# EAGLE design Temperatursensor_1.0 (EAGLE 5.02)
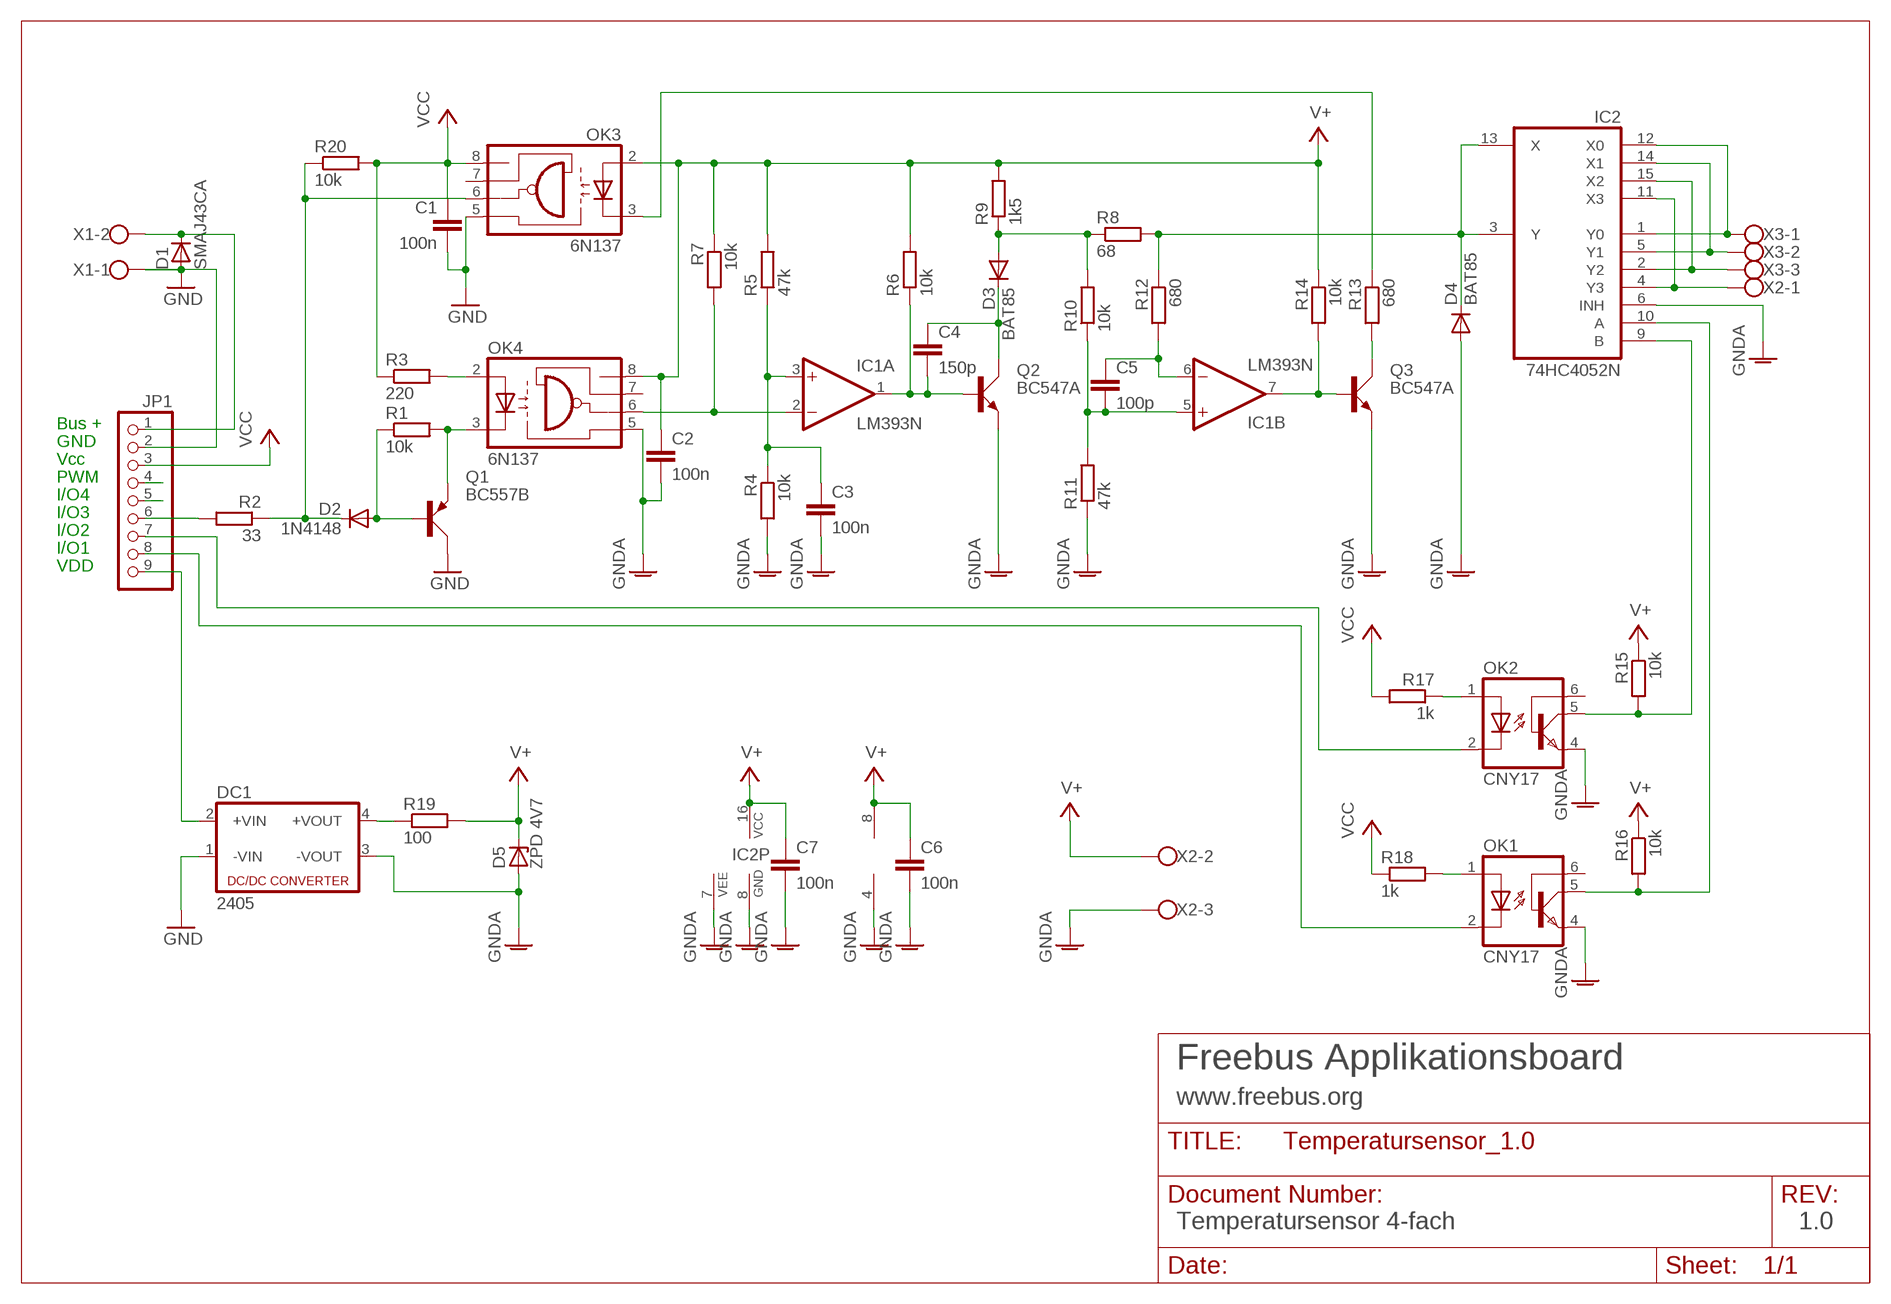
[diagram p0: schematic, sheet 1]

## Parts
C1  100n  C-EU025-024X044  [C025-024X044]
C2  100n  C-EU025-024X044  [C025-024X044]
C3  100n  C-EU025-024X044  [C025-024X044]
C4  150p  C-EU025-024X044  [C025-024X044]
C5  100p  C-EU025-024X044  [C025-024X044]
C6  100n  C-EU025-024X044  [C025-024X044]
C7  100n  C-EU025-024X044  [C025-024X044]
D1  SMAJ43CA  D-SMB  [SMB]
D2  1N4148  DIODE-D-2.5  [D-2.5]
D3  BAT85  DIODE-D-2.5  [D-2.5]
D4  BAT85  DIODE-D-7.5  [D-7.5]
D5  ZPD 4V7  ZPDSTEHEND  [ZDIODE]
DC1  2405  NME  [NME]
IC1  LM393N  [DIL08]
IC2  74HC4052N  4052N  [DIL16]
JP1  PINHD-1X9  [1X09]
OK1  CNY17  [DIL06]
OK2  CNY17  [DIL06]
OK3  6N137  HCPL2601  [DIL08]
OK4  6N137  HCPL2601  [DIL08]
Q1  BC557B  BC557  [SOT54A]
Q2  BC547A  BC547  [SOT54A]
Q3  BC547A  BC547  [SOT54A]
R1  10k  R-EU_0207/2V  [0207/2V]
R2  33  R-EU_0207/2V  [0207/2V]
R3  220  R-EU_0207/2V  [0207/2V]
R4  10k  R-EU_0207/2V  [0207/2V]
R5  47k  R-EU_0207/2V  [0207/2V]
R6  10k  R-EU_0207/2V  [0207/2V]
R7  10k  R-EU_0207/2V  [0207/2V]
R8  68  R-EU_0207/2V  [0207/2V]
R9  1k5  R-EU_0207/2V  [0207/2V]
R10  10k  R-EU_0207/2V  [0207/2V]
R11  47k  R-EU_0207/2V  [0207/2V]
R12  680  R-EU_0207/2V  [0207/2V]
R13  680  R-EU_0207/2V  [0207/2V]
R14  10k  R-EU_0207/2V  [0207/2V]
R15  10k  R-EU_0207/2V  [0207/2V]
R16  10k  R-EU_0207/2V  [0207/2V]
R17  1k  R-EU_0207/2V  [0207/2V]
R18  1k  R-EU_0207/2V  [0207/2V]
R19  100  R-EU_0207/2V  [0207/2V]
R20  10k  R-EU_0207/2V  [0207/2V]
X1  W237-02P  [W237-132]
X2  W237-3E  [W237-3E]
X3  W237-3E  [W237-3E]

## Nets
GND: C1.2 D1.2(A) DC1.1(-VIN) JP1.2 OK3.5(GND) Q1.C X1.1
GNDA: C2.2 C3.2 C6.2 C7.2 D4.A D5.A DC1.3(-VOUT) IC1.4(P:V-) IC2.6(INH) IC2.7(VEE) IC2.8(GND) OK1.4(EMI) OK2.4(EMI) OK4.5(GND) Q2.E Q3.E R4.2 R11.1 X2.3
IO1: JP1.8 OK1.2(C)
IO2: JP1.7 OK2.2(C)
IO3: JP1.6 R2.2
IO4: JP1.5
N$1: OK4.2(A) R3.2
N$2: OK4.3(C) Q1.E R1.2
N$3: D2.A Q1.B R1.1
N$4: D1.1(C) JP1.1 X1.2
N$5: D2.C OK3.6(OUT) R2.1 R20.1
N$6: IC2.1(Y0) IC2.12(X0) X3.1
N$7: IC1.2(A:-IN) OK4.6(OUT) R7.2
N$9: D4.C IC2.3(Y) IC2.13(X) R8.2 R12.1
N$10: D3.A R8.1 R9.1 R10.2
N$11: C3.1 IC1.3(A:+IN) R4.1 R5.1
N$12: IC2.5(Y1) IC2.14(X1) X3.2
N$13: C5.2 IC1.5(B:+IN) R10.1 R11.2
N$14: C4.2 IC1.1(A:OUT) Q2.B R6.1
N$15: C4.1 D3.C Q2.C
N$17: IC2.2(Y2) IC2.15(X2) X3.3
N$19: C5.1 IC1.6(B:-IN) R12.2
N$20: IC2.4(Y3) IC2.11(X3) X2.1
N$21: IC1.7(B:OUT) Q3.B R14.2
N$22: OK3.3(C) R13.1
N$23: Q3.C R13.2
N$24: IC2.9(B) OK2.5(COL) R15.2
N$25: IC2.10(A) OK1.5(COL) R16.2
N$27: OK2.1(A) R17.1
N$28: OK1.1(A) R18.2
N$29: DC1.4(+VOUT) R19.1
PWM: JP1.4
V+: C2.1 C6.1 C7.1 D5.C IC1.8(P:V+) IC2.16(VCC) OK3.2(A) OK4.8(VCC) R5.2 R6.2 R7.1 R9.2 R14.1 R15.1 R16.1 R19.2 X2.2
VCC: C1.1 JP1.3 OK3.8(VCC) R3.1 R17.2 R18.1 R20.2
VDD_IN: DC1.2(+VIN) JP1.9
Unconnected: OK1.6(BAS) OK2.6(BAS) OK3.7(EN) OK4.7(EN)

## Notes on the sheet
- Bus +
- GND
- Vcc
- PWM
- I/O4
- I/O3
- I/O2
- I/O1
- VDD
- Freebus Applikationsboard
- www.freebus.org
- Temperatursensor 4-fach | 1.0

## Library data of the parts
C1-C7 = resistor:C-EU: CAPACITOR, European symbol
D1 = semicon-smd-ipc:D-: DIODE
D2-D4 = diode:DIODE-: DIODE
D5 = diode:ZPD: Z DIODE
DC1 = dc-dc-converter:NME: DC-DC CONVERTER
IC1 = linear:LM393: COMPARATOR
IC2 = 40xx:4052: Dual 4-channel ANALOG MULTIPLEXER
JP1 = pinhead:PINHD-1X9: PIN HEADER
OK1 OK2 = optocoupler:CNY17: SIEMENS OPTO COUPLER
OK3 OK4 = optocoupler:HCPL2601: HEWLETT PACKARD OPTO COUPLER
Q1 = transistor-small-signal:BC557: PNP TRANSISTOR
Q2 Q3 = transistor-small-signal:BC547: NPN TRANSISTOR
R1-R20 = resistor:R-EU_: RESISTOR, European symbol
X1 = con-wago-508:W237-02P: WAGO SREW CLAMP
X2 X3 = con-wago-508:W237-3E: WAGO SREW CLAMP

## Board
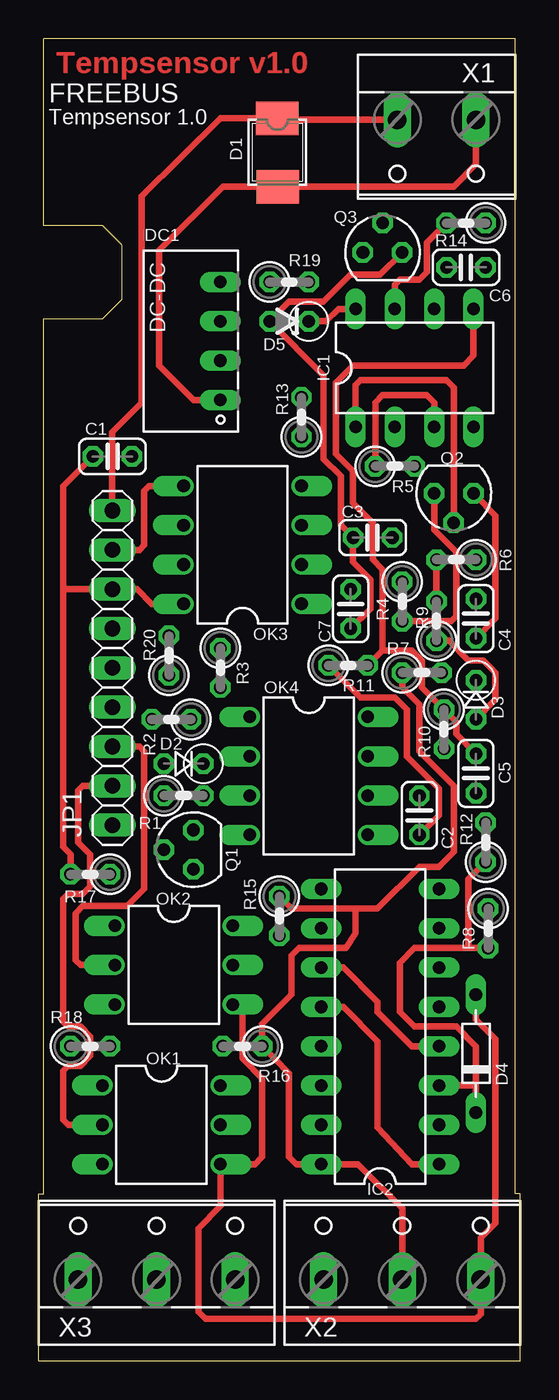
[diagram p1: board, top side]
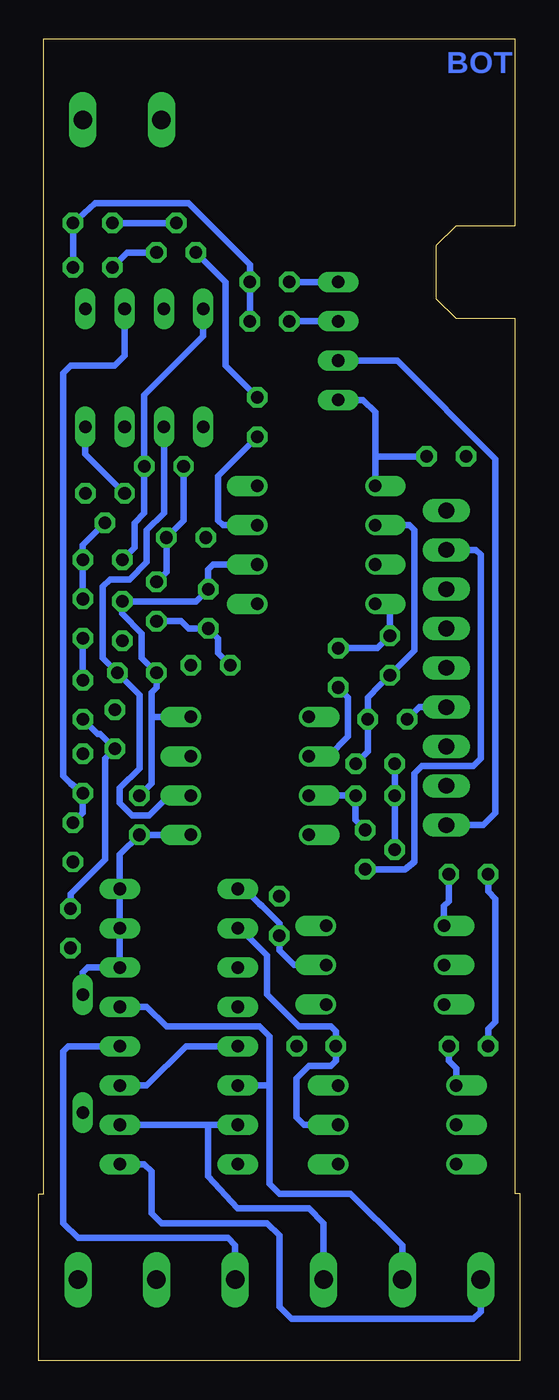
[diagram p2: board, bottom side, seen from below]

Size 31.11 x 85.41 mm. Coordinates in mm from the lower left corner, seen from the top.
Outline: 0,0 0,10.79 0.32,10.79 0.32,67.31 4.13,67.31 5.4,68.58 5.4,72.07 4.13,73.34 0.32,73.34 0.32,85.41 30.8,85.41 30.8,10.79 31.11,10.79 31.11,0 0,0
Copper layers (1*16): Top 0.035mm / dielectric 1.5mm / Bottom 0.035mm
Design rules "default *": minimum track width 10mil, minimum drill 24mil, track to track 12mil, track to pad 12mil, pad to pad 12mil, via to via 12mil, smd to smd 8mil, copper to edge 40mil, drill to drill 8mil, minimum pad ring 10mil, minimum via ring 8mil, stop-mask expansion 4mil, vias tented up to drill 0mil, thermal gap 10mil

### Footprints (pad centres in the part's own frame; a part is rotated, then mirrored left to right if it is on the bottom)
C025-024X044 = drill 0.813 octagon: 1 -1.27,0; 2 1.27,0
SMB = smd 2.159 x 2.743: 1 -2.311,-0.127; 2 2.108,-0.102
D-2.5 = drill 0.813 octagon: A 1.27,0; C -1.27,0
D-7.5 = drill 0.813 long: A 3.81,0; C -3.81,0
ZDIODE = drill 0.813 octagon: A 1.27,0; C -1.27,0
NME = drill 0.813 long: 1 0,3.81; 2 0,1.27; 3 0,-1.27; 4 0,-3.81
DIL08 = drill 0.813 long: 1 -3.81,-3.81; 2 -1.27,-3.81; 3 1.27,-3.81; 4 3.81,-3.81; 5 3.81,3.81; 6 1.27,3.81; 7 -1.27,3.81; 8 -3.81,3.81
DIL16 = drill 0.813 long: 1 -8.89,-3.81; 2 -6.35,-3.81; 3 -3.81,-3.81; 4 -1.27,-3.81; 5 1.27,-3.81; 6 3.81,-3.81; 7 6.35,-3.81; 8 8.89,-3.81; 9 8.89,3.81; 10 6.35,3.81; 11 3.81,3.81; 12 1.27,3.81; 13 -1.27,3.81; 14 -3.81,3.81; 15 -6.35,3.81; 16 -8.89,3.81
1X09 = drill 1.016 long: 1 -10.16,0; 2 -7.62,0; 3 -5.08,0; 4 -2.54,0; 5 0,0; 6 2.54,0; 7 5.08,0; 8 7.62,0; 9 10.16,0
DIL06 = drill 0.813 offset: 1 -2.54,-3.81; 2 0,-3.81; 3 2.54,-3.81; 4 2.54,3.81; 5 0,3.81; 6 -2.54,3.81
DIL08' = drill 0.813 offset: 1 -3.81,-3.81; 2 -1.27,-3.81; 3 1.27,-3.81; 4 3.81,-3.81; 5 3.81,3.81; 6 1.27,3.81; 7 -1.27,3.81; 8 -3.81,3.81
SOT54A = drill 0.813 octagon: B 0,1.905; C -1.27,0; E 1.27,0
0207/2V = drill 0.813 octagon: 1 -1.27,0; 2 1.27,0
W237-132 = drill 1.194 long: 1 -2.54,-0.635; 2 2.54,-0.635
W237-3E = drill 1.194 long: 1 -5.08,-0.635; 2 0,-0.635; 3 5.08,-0.635

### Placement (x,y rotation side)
C1  4.76,58.42 0 top
C2  24.61,35.24 270 top
C3  21.59,53.18 180 top
C4  28.26,47.94 90 top
C5  28.26,37.94 90 top
C6  27.62,70.64 180 top
C7  20.16,48.58 270 top
D1  15.56,77.95 270 top
D2  9.37,38.58 180 top
D3  28.26,42.7 270 top
D4  28.26,19.84 90 top
D5  16.19,67.15 180 top
DC1  11.75,65.88 180 top
IC1  24.29,64.14 0 top
IC2  22.07,21.59 90 top
JP1  4.76,44.77 270 top
OK1  7.94,15.24 270 top
OK2  8.73,25.56 270 top
OK3  6N137  [DIL08']  13.18,52.71 90 top
OK4  6N137  [DIL08']  17.46,37.78 270 top
Q1  10,33.02 90 top
Q2  26.83,56.04 180 top
Q3  22.22,71.6 0 top
R1  9.37,36.51 0 top
R2  8.57,41.43 180 top
R3  11.75,44.77 270 top
R4  23.5,49.05 270 top
R5  23.02,57.79 0 top
R6  26.99,51.75 180 top
R7  24.76,44.45 0 top
R8  29.05,27.94 270 top
R9  25.72,47.78 90 top
R10  26.19,40.8 270 top
R11  20,44.93 0 top
R12  28.89,33.5 90 top
R13  16.99,60.96 90 top
R14  27.62,73.5 180 top
R15  15.56,28.73 270 top
R16  13.18,20.32 180 top
R17  3.33,31.43 180 top
R18  3.33,20.32 0 top
R19  16.19,69.69 0 top
R20  8.41,45.56 90 top
X1  25.72,79.53 180 top
X2  23.49,5.87 0 top
X3  7.62,5.87 0 top

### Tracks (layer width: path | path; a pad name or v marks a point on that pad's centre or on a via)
GND
  Top 0.406: DC1.1 10,62.07 7.78,64.29 7.78,71.75 11.91,75.84 D1.2 26.83,75.84 28.26,77.31 X1.1 | JP1.2 6.51,52.39 6.83,52.71 6.83,56.2 7.14,56.52 OK3.5
  Bottom 0.406: 9.37,58.42 C1.2 | 9.37,58.42 9.37,61.28 10.16,62.07 DC1.1 | Q1.C 7.46,31.75 6.83,32.23 6.83,35.08 6.83,35.4 6.83,36.67 6.83,37.94 6.35,38.42 3.02,38.42 2.54,38.89 2.54,52.07 2.86,52.39 JP1.2 | OK3.5 9.37,58.42
GNDA
  Top 0.406: C7.2 21.43,48.58 21.43,50.48 20.32,51.59 C3.2 19.53,53.98 19.53,57.15 18.42,58.26 18.42,63.66 D5.A 16.19,68.42 18.42,68.42 20.16,70.17 22.07,70.17 Q3.E | R4.2 26.67,47.78 26.99,48.1 26.99,52.23 25.56,53.66 Q2.E | Q3.E | C2.2 25.88,35.24 25.88,36.99 23.81,39.05 | 23.81,39.05 | 23.81,39.05 | 23.81,39.05 | 23.81,39.05 23.81,42.07 23.02,42.86 20.8,42.86 R11.1 | R11.1 | R11.1 | OK2.4 13.18,23.02 13.18,22.86 13.18,22.7 13.18,19.53 14.45,18.26 14.45,13.18 13.97,12.7 OK1.4 11.75,10 10.32,8.57 10.32,3.17 10.79,2.7 28.26,2.7 28.58,3.02 X2.3 28.58,7.94 29.53,8.89 29.53,20.8 28.26,22.07 28.26,23.34 D4.A
  Bottom 0.406: OK4.5 24.45,33.97 C2.2 | C2.2 | IC2.8 25.88,32.7 C2.2 | R4.2 21.91,47.78 21.43,47.31 C7.2 19.53,46.67 19.53,45.72 R11.1 | Q3.E | C6.2 25.4,71.6 Q3.E | D5.A DC1.3 | IC2.8 | IC2.7 IC2.8 | IC2.6 | IC2.7 | IC2.6 IC2.7 | IC2.6 27.94,25.4 28.26,25.08 D4.A | D4.A | Q2.E | Q2.E 28.1,58.58 IC1.4
IO1
  Top 0.406: JP1.8 2.86,37.15 2.54,36.83 2.54,33.5 3.33,32.7 3.33,30.64 2.86,30.16 1.9,30.16 1.59,29.84 1.59,21.91 1.9,21.59 2.7,21.59 3.33,20.95 3.33,19.68 2.7,19.05 1.9,19.05 1.59,18.73 1.59,15.56 1.9,15.24 OK1.2
IO2
  Top 0.406: JP1.7 6.51,39.69 6.83,39.37 6.83,30.48 5.71,29.37 2.86,29.37 2.38,28.89 2.38,25.88 2.7,25.56 4.13,25.56 OK2.2
IO3
  Bottom 0.406: R2.2 6.51,42.23 JP1.6 | R2.2
N$1
  Bottom 0.406: OK4.2 12.38,39.05 11.11,40.32 11.11,42.86 R3.2 | R3.2
N$2
  Bottom 0.406: OK4.3 10.79,36.51 R1.2 | R1.2 | R1.2 10.64,34.92 Q1.E
N$3
  Bottom 0.406: Q1.B 8.1,37.47 | D2.A 8.1,37.78 8.1,37.47 | 8.1,37.47 R1.1
N$4
  Top 0.406: X1.2 15.56,80.17 15.56,80.42 D1.1 11.75,80.26 6.67,75.25 6.67,61.91 4.76,60.01 JP1.1
N$5
  Bottom 0.406: D2.C 9.84,39.37 9.84,40.48 R2.1 | OK3.6 7.14,53.98 6.83,53.66 6.83,45.88 6.99,45.72 R20.1 9.05,43.66 9.84,42.86 R2.1 | R2.1
N$6
  Top 0.406: IC2.1 24.13,12.7 21.91,15.08 21.91,20.64 19.68,22.86 IC2.12
  Bottom 0.406: X3.1 2.54,3.17 3.02,2.7 14.76,2.7 15.56,3.49 15.56,8.1 16.35,8.89 23.18,8.89 23.81,9.53 23.81,12.22 24.29,12.7 IC2.1 | IC2.1
N$7
  Bottom 0.406: OK4.6 | OK4.6 | OK4.6 22.7,36.51 23.97,35.24 25.08,35.24 25.88,36.04 25.88,36.99 24.61,38.26 24.61,43.02 R7.2 26.99,45.4 26.99,50.01 26.51,50.48 25.24,50.48 24.13,51.59 24.13,53.66 23.02,54.77 23.02,56.83 23.02,57.94 IC1.2
N$9
  Top 0.406: IC2.3 28.26,17.78 | 28.26,17.78 D4.C | D4.C | 28.26,17.78 28.26,20.32 26.99,21.59 24.29,21.59 23.34,22.54 23.34,25.72 24.29,26.67 26.99,26.67 27.62,26.67 R8.2 | R8.2 | R12.1 27.78,31.11 27.78,26.67 R8.2 | R8.2 | R8.2 | R8.2
  Bottom 0.406: IC2.3 24.13,17.78 21.59,20.32 IC2.13
N$10
  Top 0.406: R9.1 26.51,46.51 27.78,45.24 28.58,45.24 28.73,45.24 29.53,44.45 29.53,42.7 D3.A
  Bottom 0.406: D3.A 27.3,40.48 27.15,40.48 26.83,40.16 R10.2 26.83,38.89 26.83,35.88 | R8.1 29.05,30.16 27.78,31.43 26.83,32.38 26.83,35.88 | 26.83,35.88 26.83,35.56
N$11
  Top 0.406: R5.1 21.75,61.91 22.22,62.39 22.38,62.39 25.08,62.39 25.56,61.91 IC1.3
  Bottom 0.406: R4.1 22.86,50.96 C3.1 21.75,54.29 R5.1
N$12
  Bottom 0.406: X3.2 7.62,7.46 10.95,10.79 15.56,10.79 16.19,11.43 16.19,17.78 | 16.19,17.78 IC2.14 | IC2.5 24.13,22.86 22.86,21.59 16.83,21.59 16.19,20.95 16.19,17.78
N$13
  Top 0.406: 22.22,45.88 22.22,51.12 21.59,51.75 21.59,54.13 | 21.59,54.13 | 21.59,54.13 20.32,55.4 20.32,57.47 19.21,58.58 19.21,63.18 20.32,64.29 27.46,64.29 28.1,64.93 IC1.5 | C5.2 | C5.2 26.99,40.48 26.99,41.28 R10.1 25.4,42.86 | 25.4,42.86 | 25.4,42.86 24.77,43.5 24.77,45.24 24.13,45.88 22.22,45.88 | 22.22,45.88 R11.2 | 22.22,45.88
N$14
  Top 0.406: Q2.B 26.83,56.2 26.83,58.26 26.83,62.87 26.35,63.34 20.8,63.34 20.48,63.02 IC1.1
  Bottom 0.406: R6.1 28.26,49.85 C4.2 | R6.1 | R6.1 28.26,52.71 27.78,53.18 Q2.B
N$15
  Top 0.406: C4.1 29.53,47.94 29.53,48.26 29.53,54.61 28.26,55.88 | 28.26,55.88 Q2.C | 28.26,55.88
  Bottom 0.406: D3.C 28.26,44.45 C4.1
N$17
  Bottom 0.406: IC2.2 | 20.16,15.24 IC2.15 | 20.16,15.24 IC2.2 | X3.3 12.7,8.89 13.65,9.84 18.26,9.84 20.16,11.91 20.16,15.24
N$19
  Bottom 0.406: IC1.6 25.56,64.93 26.19,64.29 29.05,64.29 29.53,63.82 29.53,52.23 29.53,37.78 29.05,37.31 C5.1 28.26,35.4 R12.2 | R12.2 | R12.2
N$20
  Top 0.406: IC2.4 24.13,20.32 21.91,22.54 21.91,23.18 19.68,25.4 IC2.11
  Bottom 0.406: X2.1 18.42,7.46 18.89,7.94 28.58,7.94 29.53,8.89 29.53,20 29.21,20.32 IC2.4
N$21
  Top 0.406: R14.2 25.08,72.23 25.08,70.33 24.61,69.85 23.34,69.85 23.02,69.53 IC1.7
  Bottom 0.406: Q3.B | R14.2 Q3.B
N$22
  Bottom 0.406: OK3.3 19.21,53.98 19.53,54.29 19.53,57.15 R13.1
N$23
  Bottom 0.406: R13.2 19.05,64.29 19.05,69.69 Q3.C | Q3.C
N$24
  Bottom 0.406: OK2.5 14.61,25.56 15.56,26.51 R15.2 | 15.4,27.62 | 18.1,30.48 IC2.9 17.78,30.48 16.83,29.53 16.67,29.37 15.56,28.26 R15.2 | R15.2 15.4,27.62
N$25
  Bottom 0.406: OK1.5 | OK1.5 13.97,15.24 14.45,15.72 14.45,18.26 13.65,19.05 12.22,19.05 11.91,19.37 R16.2 11.91,21.27 12.22,21.59 14.29,21.59 16.35,23.65 16.35,26.19 18.1,27.94 IC2.10
N$27
  Bottom 0.406: R17.1 4.6,29.69 4.92,29.37 OK2.1
N$28
  Bottom 0.406: R18.2 4.6,19.37 4.13,18.89 OK1.1
N$29
  Bottom 0.406: DC1.4 R19.1
V+
  Top 0.406: X2.2 23.49,9.84 20.64,12.7 IC2.16 16.67,12.7 16.19,13.18 16.19,18.57 15.24,19.53 R16.1 14.45,21.75 16.35,23.65 16.35,26.19 16.83,26.67 19.84,26.67 20.48,27.62 20.48,29.21 | R6.2 25.72,50.01 R9.2 | 20.48,29.21 21.91,29.21 24.61,31.91 25.88,31.91 26.83,32.86 26.83,37.15 26.51,37.47 25.08,38.89 24.61,39.37 24.61,42.39 23.49,43.5 R7.1 | R7.1 | IC1.8 19.37,67.95 18.57,67.15 D5.C | R15.1 16.35,29.21 20.48,29.21 | 20.48,29.21 | 20.48,29.21
  Bottom 0.406: OK3.2 19.84,51.44 20.16,51.12 C7.1 20.96,49.05 24.29,49.05 R9.2 | R7.1 24.45,45.4 24.45,46.99 25.72,48.26 25.72,48.74 R9.2 | R9.2 | R14.1 C6.1 | R6.2 24.92,52.55 24.92,54.13 24.29,54.77 24.29,58.74 | 24.29,58.74 R5.2 | 24.29,58.74 24.29,62.39 20.48,66.2 IC1.8 | R14.1 | R14.1 27.46,74.77 21.43,74.77 17.46,70.8 R19.2 D5.C | C2.1 23.81,37.31 23.81,41.59 | OK4.8 23.81,41.59 | OK4.8 | 23.81,41.59 23.81,43.18 23.49,43.5 R7.1 | R7.1
VCC
  Top 0.406: R17.2 | R17.2 2.06,32.7 1.59,33.18 1.59,49.85 | 1.59,49.85 JP1.3 6.35,49.85 7.3,48.9 OK3.8 | C1.1 1.59,56.52 1.59,49.85
  Bottom 0.406: R18.1 2.06,21.43 1.59,21.91 1.59,29.84 2.06,30.32 R17.2 | R3.1 9.21,46.04 R20.2 8.41,48.9 OK3.8
VDD_IN
  Bottom 0.406: DC1.2 7.94,64.61 1.59,58.26 1.59,35.4 2.38,34.61 JP1.9

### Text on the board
Top: Tempsensor v1.0
Bottom: BOT
tNames: FREEBUS | Tempsensor 1.0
